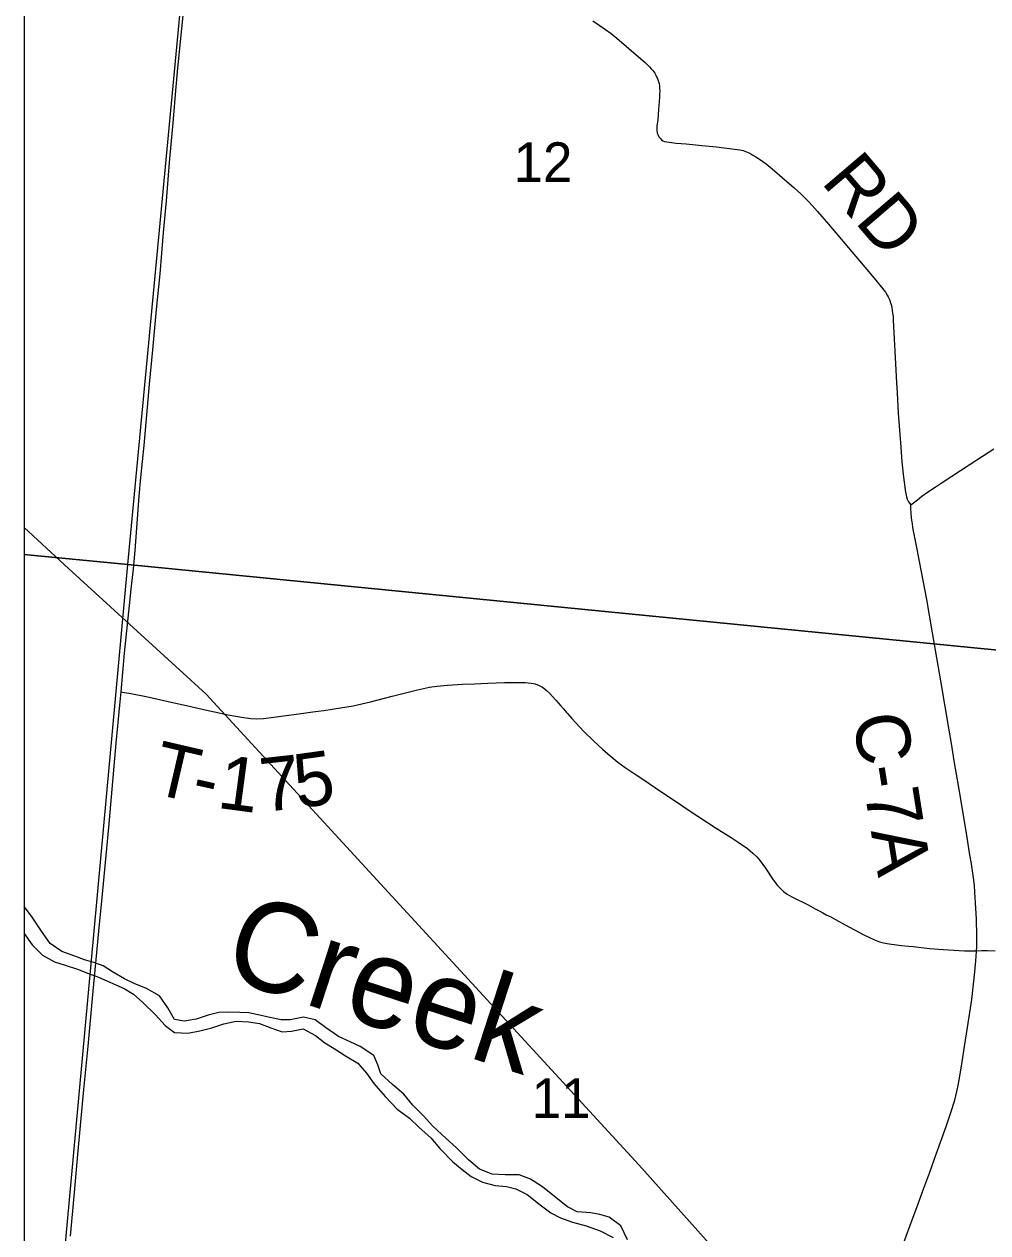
# Model space of a CAD drawing. Extents: x 0 to 1134, y 0 to 440.
# Drawn here: x 832.764 to 833.782, y 364.534 to 365.811 of the extents above; entities that cross this region are included whole.
import ezdxf

# ---------------------------------------------------------------- set-up
doc = ezdxf.new("R2010")
doc.units = 0
for name, color, linetype in [('GM_X_County_Road', 7, 'Continuous'), ('GM_X_County_Road_Text', 7, 'Continuous'), ('GM_X_Major_River', 7, 'Continuous'), ('GM_X_Minor_River', 7, 'Continuous'), ('GM_X_Minor_River_Text', 7, 'Continuous'), ('GM_X_Rail_Line', 7, 'Continuous'), ('GM_X_Section', 7, 'Continuous'), ('GM_X_Section_Text', 7, 'Continuous'), ('GM_X_State_Route', 7, 'Continuous'), ('GM_X_Township_Road', 7, 'Continuous'), ('GM_X_Township_Road_Text', 7, 'Continuous'), ('GM_X_Unincorporated', 7, 'Continuous'), ('SH_Cut_Line', 7, 'Continuous')]:
    doc.layers.add(name, color=color, linetype=linetype)

msp = doc.modelspace()

# ---------------------------------------------------------------- linework, layer by layer
at = {"layer": 'GM_X_County_Road'}
for points in [[(833.7011, 365.3032), (833.7081, 365.3087), (833.7126, 365.3125), (833.7185, 365.3168), (833.7268, 365.3222), (833.7341, 365.327), (833.7638, 365.3463), (833.7768, 365.3548), (833.7888, 365.3626)], [(833.7705, 364.8319), (833.7707, 364.8357), (833.7707, 364.8481), (833.7702, 364.8654), (833.7693, 364.8828), (833.7687, 364.894), (833.7681, 364.9008), (833.7672, 364.9092), (833.7651, 364.9239), (833.7631, 364.9355), (833.7597, 364.9563), (833.7516, 365.0047), (833.7469, 365.0329), (833.7441, 365.0488), (833.741, 365.0671), (833.7328, 365.1173), (833.7285, 365.1417), (833.7239, 365.168), (833.7177, 365.2033), (833.71, 365.2435), (833.7076, 365.2564), (833.7044, 365.2724), (833.7035, 365.2774), (833.7031, 365.2797), (833.7026, 365.2831), (833.7022, 365.2853), (833.702, 365.2871), (833.7017, 365.2896), (833.7015, 365.2914), (833.7014, 365.2932), (833.7013, 365.2954), (833.7011, 365.2989), (833.7011, 365.3032)], [(833.692, 364.5198), (833.6998, 364.5408), (833.7077, 364.5616), (833.7147, 364.5809), (833.721, 364.5978), (833.7278, 364.6171), (833.7382, 364.6463), (833.7433, 364.661), (833.7473, 364.6739), (833.7507, 364.6877), (833.7529, 364.6993), (833.7553, 364.7146), (833.7576, 364.7306), (833.7609, 364.7508), (833.7653, 364.7804), (833.7686, 364.8098), (833.7697, 364.8212), (833.7705, 364.8312), (833.7705, 364.8319)]]:
    msp.add_lwpolyline(points, dxfattribs=at)
at = {"layer": 'GM_X_Major_River'}
for points in [[(832.7638, 366.2528), (832.7638, 365.251), (832.8734, 365.2403), (832.9675, 366.2339)], [(832.7638, 365.251), (832.7638, 364.229), (832.7804, 364.2273), (832.8734, 365.2403)]]:
    msp.add_lwpolyline(points, close=True, dxfattribs=at)
at = {"layer": 'GM_X_Minor_River'}
for points in [[(832.907, 364.7842), (832.8931, 364.7921), (832.8799, 364.7974), (832.8698, 364.8022), (832.857, 364.8097), (832.8473, 364.8161), (832.8375, 364.8197), (832.8277, 364.8223), (832.8175, 364.8263), (832.8035, 364.8312), (832.7912, 364.8395), (832.782, 364.8527), (832.7717, 364.8686), (832.7638, 364.8786)], [(832.7638, 364.8503), (832.7655, 364.8478), (832.7721, 364.8381), (832.7833, 364.8272), (832.796, 364.8204), (832.807, 364.8167), (832.8202, 364.8126), (832.8319, 364.8081), (832.8424, 364.804), (832.8695, 364.7919), (832.8793, 364.786), (832.8893, 364.7774), (832.9027, 364.7641), (832.913, 364.7528), (832.9228, 364.7457), (832.9368, 364.745), (832.9494, 364.7473), (832.9621, 364.7504), (832.9747, 364.7547), (832.9877, 364.7574), (833.001, 364.7567), (833.0124, 364.7549), (833.0245, 364.7504), (833.0365, 364.7463), (833.0465, 364.7468), (833.0587, 364.7496), (833.0718, 364.7424), (833.0815, 364.7345), (833.0913, 364.7286), (833.1036, 364.721), (833.1164, 364.7131), (833.1256, 364.7026), (833.1333, 364.6918), (833.1455, 364.6778), (833.1582, 364.6645), (833.1709, 364.6551), (833.1813, 364.6453), (833.1935, 364.6343), (833.2031, 364.6231), (833.2169, 364.6087), (833.2266, 364.6008), (833.2363, 364.5933), (833.2483, 364.5873), (833.2615, 364.584), (833.2737, 364.5829), (833.2835, 364.5804)], [(833.4016, 364.5264), (833.3944, 364.5411), (833.3821, 364.5505), (833.3722, 364.553), (833.3628, 364.5548), (833.3483, 364.5559), (833.3382, 364.5611), (833.3244, 364.5721), (833.3117, 364.5823), (833.299, 364.5906), (833.2869, 364.5951), (833.2721, 364.5951), (833.2584, 364.5958), (833.2452, 364.6011), (833.2333, 364.6109), (833.2207, 364.6238), (833.2099, 364.6336), (833.1954, 364.6469), (833.1861, 364.657), (833.1746, 364.6687), (833.165, 364.6803), (833.1531, 364.6905), (833.1408, 364.7019), (833.1376, 364.7114), (833.1333, 364.7214), (833.1191, 364.7306), (833.1082, 364.7358), (833.0962, 364.7414), (833.0823, 364.7509), (833.0715, 364.7591), (833.059, 364.7617), (833.0449, 364.759), (833.0353, 364.7589), (833.0236, 364.7615), (833.0111, 364.7644), (833.0013, 364.7662), (832.9918, 364.7668), (832.98, 364.7671), (832.9697, 364.7666), (832.9582, 364.7639), (832.9456, 364.7596), (832.933, 364.7576), (832.9227, 364.7594), (832.9158, 364.7718), (832.907, 364.7842)], [(833.2835, 364.5804), (833.2955, 364.5744), (833.3093, 364.5634), (833.3205, 364.5551), (833.3307, 364.5495), (833.3435, 364.545), (833.3579, 364.5412), (833.3726, 364.5359), (833.3865, 364.5287)]]:
    msp.add_lwpolyline(points, dxfattribs=at)
at = {"layer": 'GM_X_Rail_Line'}
msp.add_lwpolyline([(832.7638, 365.2794), (832.8063, 365.2399), (832.9561, 365.1033), (833.4135, 364.6058), (833.5859, 364.4129), (833.6728, 364.3143), (833.7792, 364.2364), (833.8789, 364.1723), (833.9716, 364.1241), (834.0271, 364.1007), (834.1167, 364.0808), (834.2132, 364.0834), (834.5593, 364.1019), (834.7644, 364.0946), (834.7978, 364.0893)], dxfattribs=at)
at = {"layer": 'GM_X_Section'}
for points in [[(833.9717, 366.1415), (833.8824, 365.141), (832.8734, 365.2403), (832.9675, 366.2339)], [(832.8734, 365.2403), (833.8824, 365.141), (833.7939, 364.1431), (832.7804, 364.2273)]]:
    msp.add_lwpolyline(points, close=True, dxfattribs=at)
at = {"layer": 'GM_X_State_Route'}
msp.add_lwpolyline([(832.8127, 364.5302), (832.817, 364.5765), (832.8205, 364.6167), (832.827, 364.6854), (832.8315, 364.7311), (832.8343, 364.762), (832.8368, 364.7893), (832.8396, 364.819), (832.8432, 364.8567), (832.8454, 364.8808), (832.8511, 364.9402), (832.8532, 364.9624), (832.8612, 365.0514), (832.8648, 365.0916), (832.8662, 365.1057), (832.87, 365.1465), (832.8736, 365.1835), (832.875, 365.197), (832.8768, 365.2143), (832.8794, 365.2358), (832.881, 365.2551), (832.8854, 365.3126), (832.8872, 365.3322), (832.8907, 365.366), (832.8963, 365.4308), (832.8998, 365.4672), (832.9038, 365.5099), (832.9074, 365.5476), (832.9112, 365.5914), (832.9141, 365.6246), (832.9175, 365.6654), (832.9216, 365.7111), (832.9241, 365.7414), (832.9263, 365.7649), (832.9342, 365.8458)], dxfattribs=at)
at = {"layer": 'GM_X_Township_Road'}
for points in [[(833.365, 365.8149), (833.3784, 365.8059), (833.3843, 365.8015), (833.3902, 365.7968), (833.4029, 365.7857), (833.4108, 365.779), (833.4201, 365.771), (833.4249, 365.7663), (833.4265, 365.7644), (833.4281, 365.7626), (833.4302, 365.7596), (833.4313, 365.7576), (833.4323, 365.7558), (833.4331, 365.7539), (833.434, 365.7519), (833.4344, 365.7506), (833.4348, 365.7489), (833.4352, 365.7459), (833.4354, 365.7433), (833.4355, 365.7409), (833.4353, 365.7376), (833.4352, 365.7341), (833.4342, 365.7211), (833.4334, 365.7105), (833.4326, 365.7036), (833.4326, 365.6994), (833.433, 365.6964), (833.4338, 365.6941), (833.4346, 365.6924), (833.4362, 365.6905), (833.4375, 365.6892), (833.439, 365.6883), (833.4407, 365.6876), (833.4431, 365.6871), (833.4529, 365.6858), (833.4634, 365.6848), (833.4801, 365.6832), (833.4956, 365.6817), (833.5147, 365.6795), (833.5202, 365.6786), (833.5239, 365.6778), (833.5274, 365.6766), (833.5308, 365.675), (833.534, 365.6731), (833.5371, 365.6712), (833.541, 365.6687), (833.548, 365.6637), (833.5543, 365.6587), (833.5675, 365.6474), (833.5778, 365.6384), (833.5846, 365.632), (833.5934, 365.6232), (833.6022, 365.6136), (833.614, 365.6001), (833.6351, 365.575), (833.6543, 365.5522), (833.6658, 365.5387), (833.6679, 365.536), (833.67, 365.5334), (833.6723, 365.5304), (833.6741, 365.528), (833.6761, 365.5249), (833.677, 365.5231), (833.678, 365.521), (833.6786, 365.5192), (833.6795, 365.5169), (833.68, 365.515), (833.6807, 365.5121), (833.6811, 365.5093), (833.6817, 365.506), (833.6821, 365.5023), (833.6824, 365.4987), (833.6844, 365.459), (833.6858, 365.4324), (833.6864, 365.4218), (833.6876, 365.4001), (833.6902, 365.3642), (833.6914, 365.3487), (833.6931, 365.3326), (833.6945, 365.3221), (833.6951, 365.3187), (833.6957, 365.3154), (833.6965, 365.3119), (833.697, 365.3095), (833.6985, 365.3065), (833.7011, 365.3032)], [(832.8662, 365.1057), (832.8698, 365.105), (832.8766, 365.1038), (832.8927, 365.1006), (832.9222, 365.0942), (832.9354, 365.0913), (832.946, 365.0888), (832.955, 365.0866), (832.965, 365.0845), (832.9795, 365.0813), (832.9935, 365.0788), (833.0032, 365.0774), (833.0093, 365.077), (833.0166, 365.0774), (833.0277, 365.0788), (833.0461, 365.0814), (833.0541, 365.0824), (833.0688, 365.0844), (833.0744, 365.0851), (833.0805, 365.0859), (833.0981, 365.0888), (833.1117, 365.0909), (833.1298, 365.0952), (833.1526, 365.1011), (833.1797, 365.1079), (833.1921, 365.1106), (833.2, 365.1118), (833.2111, 365.1129), (833.2272, 365.1138), (833.2402, 365.1143), (833.2464, 365.1145), (833.2537, 365.1149), (833.2714, 365.1156), (833.2857, 365.1157), (833.2932, 365.1154), (833.2997, 365.1149), (833.3038, 365.1141), (833.3082, 365.1125), (833.3108, 365.1111), (833.3126, 365.1098), (833.3156, 365.1076), (833.319, 365.1044), (833.3259, 365.097), (833.3308, 365.0914), (833.3339, 365.0877), (833.337, 365.084), (833.3379, 365.0828), (833.3428, 365.0774), (833.3555, 365.0639), (833.3655, 365.0538), (833.375, 365.0449), (833.3806, 365.04), (833.3912, 365.0314), (833.3991, 365.0256), (833.4084, 365.0194), (833.4198, 365.0118), (833.4346, 365.0019), (833.4534, 364.9895), (833.4667, 364.9803), (833.4952, 364.9617), (833.5109, 364.9518), (833.5186, 364.9467), (833.5283, 364.94), (833.5341, 364.9352), (833.5382, 364.9312), (833.5418, 364.9269), (833.5472, 364.9193), (833.5555, 364.9069), (833.56, 364.9011), (833.5638, 364.8971), (833.5665, 364.8947), (833.5704, 364.8917), (833.5751, 364.8889), (833.5923, 364.8804), (833.5999, 364.8763), (833.6049, 364.8737), (833.6081, 364.872), (833.6113, 364.8701), (833.6163, 364.8677), (833.6212, 364.865), (833.6315, 364.8593), (833.6507, 364.8492), (833.6624, 364.8435), (833.6679, 364.8414), (833.672, 364.8403), (833.678, 364.8392), (833.6909, 364.8377), (833.6984, 364.8368), (833.7033, 364.8363), (833.7207, 364.8344), (833.7352, 364.8332), (833.7575, 364.8319), (833.7652, 364.8318), (833.7705, 364.8319)], [(833.7705, 364.8319), (833.7761, 364.8322), (833.7819, 364.8323), (833.7901, 364.832)]]:
    msp.add_lwpolyline(points, dxfattribs=at)
at = {"layer": 'GM_X_Unincorporated'}
msp.add_lwpolyline([(832.7638, 366.2539), (832.7638, 360.1912)], dxfattribs=at)
at = {"layer": 'SH_Cut_Line'}
msp.add_lwpolyline([(832.7638, 369.3181), (832.7638, 360.1912)], dxfattribs=at)

# ---------------------------------------------------------------- texts
at = {"layer": 'GM_X_County_Road_Text'}
msp.add_text('C-7A', height=0.05682, rotation=279.0255, dxfattribs=at).set_placement((833.6394, 365.0795))
at = {"layer": 'GM_X_Minor_River_Text'}
msp.add_text('Creek', height=0.0947, rotation=341.9557, dxfattribs=at).set_placement((832.9705, 364.805))
at = {"layer": 'GM_X_Section_Text'}
for s, p in [('12', (833.281, 365.6447)), ('11', (833.3002, 364.6553))]:
    msp.add_text(s, height=0.04186, rotation=0, dxfattribs=at).set_placement(p)
at = {"layer": 'GM_X_Township_Road_Text'}
for s, height, rotation, p in [('RD', 0.05682, 310.494, (833.6051, 365.6444)), ('T', 0.0568, 346.918, (832.8966, 364.999)), ('5', 0.0568, 7.9102, (833.0528, 364.9825)), ('1', 0.0568, 352.4081, (832.9666, 364.9832)), ('7', 0.0568, 6.349, (833.0163, 364.9785)), ('-', 0.0568, 347.3538, (832.9384, 364.9893))]:
    msp.add_text(s, height=height, rotation=rotation, dxfattribs=at).set_placement(p)

doc.saveas('drawing.dxf')
